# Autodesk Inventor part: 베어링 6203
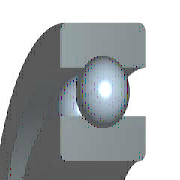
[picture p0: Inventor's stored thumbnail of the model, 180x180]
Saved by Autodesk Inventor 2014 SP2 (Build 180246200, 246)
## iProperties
IsCustomPart: 0
Created: 2016-04
Part Number: 베어링 6203
Material: 알루미늄 6061
Description: 깊은 그루브 볼 베어링
Document SubType Name: Modeling
Standard: KS B 2023
Designer: mdu
Standards Organization: KS
Language: ko-KR
Size Designation: 6203 - 17 x 40 x 12
Categories: <MemberInstance><Categories><Category DisplayName="샤프트 부품" InternalName="7f7aeb1f-a693-4053-b835-cee3144e0d98" Mnemonic="SHFT"><Category DisplayName="베어링" Inter
Density: 2.71 g/cm^3
Mass: 22.4044 g
Surface Area: 64.3582 cm^2
Volume: 8.26729 cm^3
Appearance: 알루미늄 - 평지
Author: mdu
Revision Number: 1
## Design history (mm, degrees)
sketch "스케치" dims "d0" = 5.98 (= -0.26 x WD + 0.26 x BD)
  geometry: L1 (3.01, 14.25)-(8.99, 14.25); L2 (6, 14.25)-(6, 11.26); L3 (6, 14.25)-(6, 17.24); L4 (3.778, 12.249)-(0, 12.249); L5 (0, 8.5)-(12, 8.5); L6 (3.778, 16.251)-(0, 16.251); L7 (0, 20)-(12, 20); L8 (12, 8.5)-(12, 12.249); L9 (8.222, 12.249)-(12, 12.249); L10 (8.222, 16.251)-(12, 16.251); L11 (12, 20)-(12, 16.251); L12 (-1.4, 0)-(8.4, 0) reference; L13 (0, -0.3)-(0, 5.3) reference
  constraints: 22 end point, 4 point on line, 2 collinear, 2 perpendicular, 2 symmetric about line, 1 midpoint, 1 parallel, 14 other
  dimensions: "d9" = 17 diameter of L5 L12 (= WD); "d11" = 40 diameter of L7 L12 (= BD); "d12" = 12 distance between parallel lines of L8 L13 (= KB); "d13" = 24.498 diameter of L9 L12 (= 0.326 x BD + 0.674 x WD)
revolve "본체" stored, may be unused: angle "d6" = 90 deg
revolve "볼" stored, may be unused: angle "d7" = 90 deg
pattern_circular "IDS_ARRAYBALL[SIMPL:T]" dims angle "d3" = 360 deg
body "Solid1"
fillet "모깎기1" dims "d1" = 0.6 (= KRS)
other parameters: "WD" = 17 [user parameter; used in 5 equation terms], "BD" = 40 [user parameter; used in 5 equation terms], "KB" = 12 [user parameter; used in 1 equation term], "KRS" = 0.6 [user parameter; used in 1 equation term], "d4" = 0, "d5" = 0, "d8" = 0, "d14" = 0, "d15" = 0, "BBA" = 0 [user parameter], "BC0" = 4750000 [user parameter], "BC" = 9560000 [user parameter], "WR" = 8.5 (= 0.5 x WD) [user parameter]
